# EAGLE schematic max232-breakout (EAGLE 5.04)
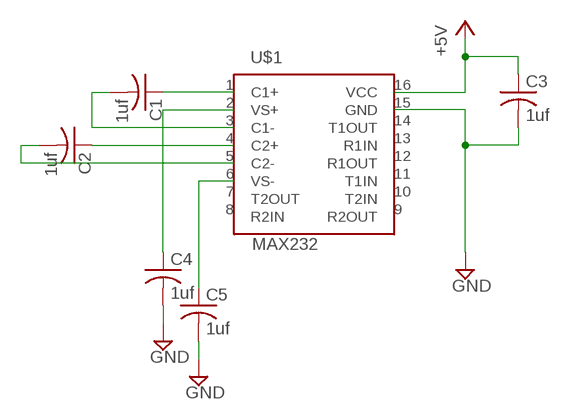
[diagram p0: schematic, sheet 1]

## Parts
C1  1uf  C-US050-025X075  [C050-025X075]
C2  1uf  C-US050-025X075  [C050-025X075]
C3  1uf  C-US050-025X075  [C050-025X075]
C4  1uf  C-US050-025X075  [C050-025X075]
C5  1uf  C-US050-025X075  [C050-025X075]
U$1  MAX232  [DIL16-3]

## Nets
+5V: C3.1 U$1.16(VCC)
GND: C3.2 C4.2 C5.2 U$1.15(GND)
N$1: C1.1 U$1.1(C1+)
N$2: C1.2 U$1.3(C1-)
N$3: C2.1 U$1.4(C2+)
N$4: C2.2 U$1.5(C2-)
N$5: C4.1 U$1.2(VS+)
N$6: C5.1 U$1.6(VS-)
Unconnected: U$1.7(T2OUT) U$1.8(R2IN) U$1.9(R2OUT) U$1.10(T2IN) U$1.11(T1IN) U$1.12(R1OUT) U$1.13(R1IN) U$1.14(T1OUT)

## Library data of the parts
C1-C5 = rcl:C-US: CAPACITOR, American symbol
U$1 = trl:MAX232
